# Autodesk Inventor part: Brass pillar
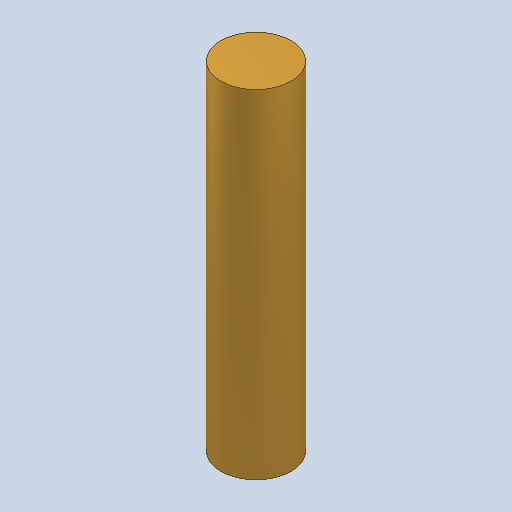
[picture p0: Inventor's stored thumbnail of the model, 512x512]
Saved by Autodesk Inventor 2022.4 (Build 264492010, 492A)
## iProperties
Created: 2023-10
Part Number: Brass pillar
Material: Brass, Soft Yellow
Document SubType Name: Modeling
Designer: tmass
Density: 8.47 g/cm^3
Appearance: Default
Author: tmass
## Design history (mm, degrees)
node "Repaired Geometry1"
  node "Sketch1"
feature "Solid1"
body "Solid2"
